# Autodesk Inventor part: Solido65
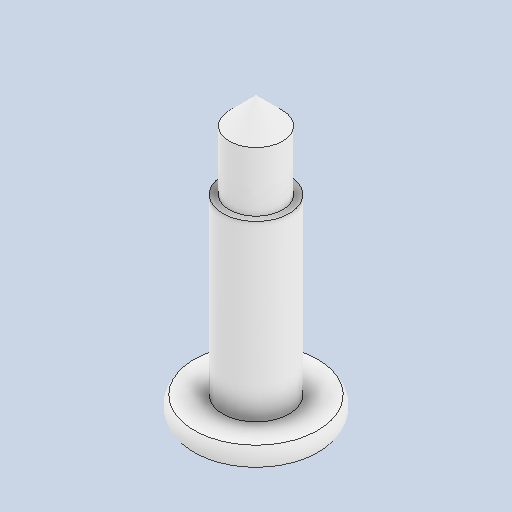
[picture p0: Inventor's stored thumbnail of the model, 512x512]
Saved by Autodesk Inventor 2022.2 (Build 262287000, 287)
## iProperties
Created: 2024-10
Part Number: Solido65
Material: Generico
Document SubType Name: Modeling
Designer: 18907419
Density: 1 g/cm^3
Appearance: Default
Author: 18907419
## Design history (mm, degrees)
feature "Solido65"
node "Solido1"
